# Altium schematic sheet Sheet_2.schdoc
size 319 x 192 mm
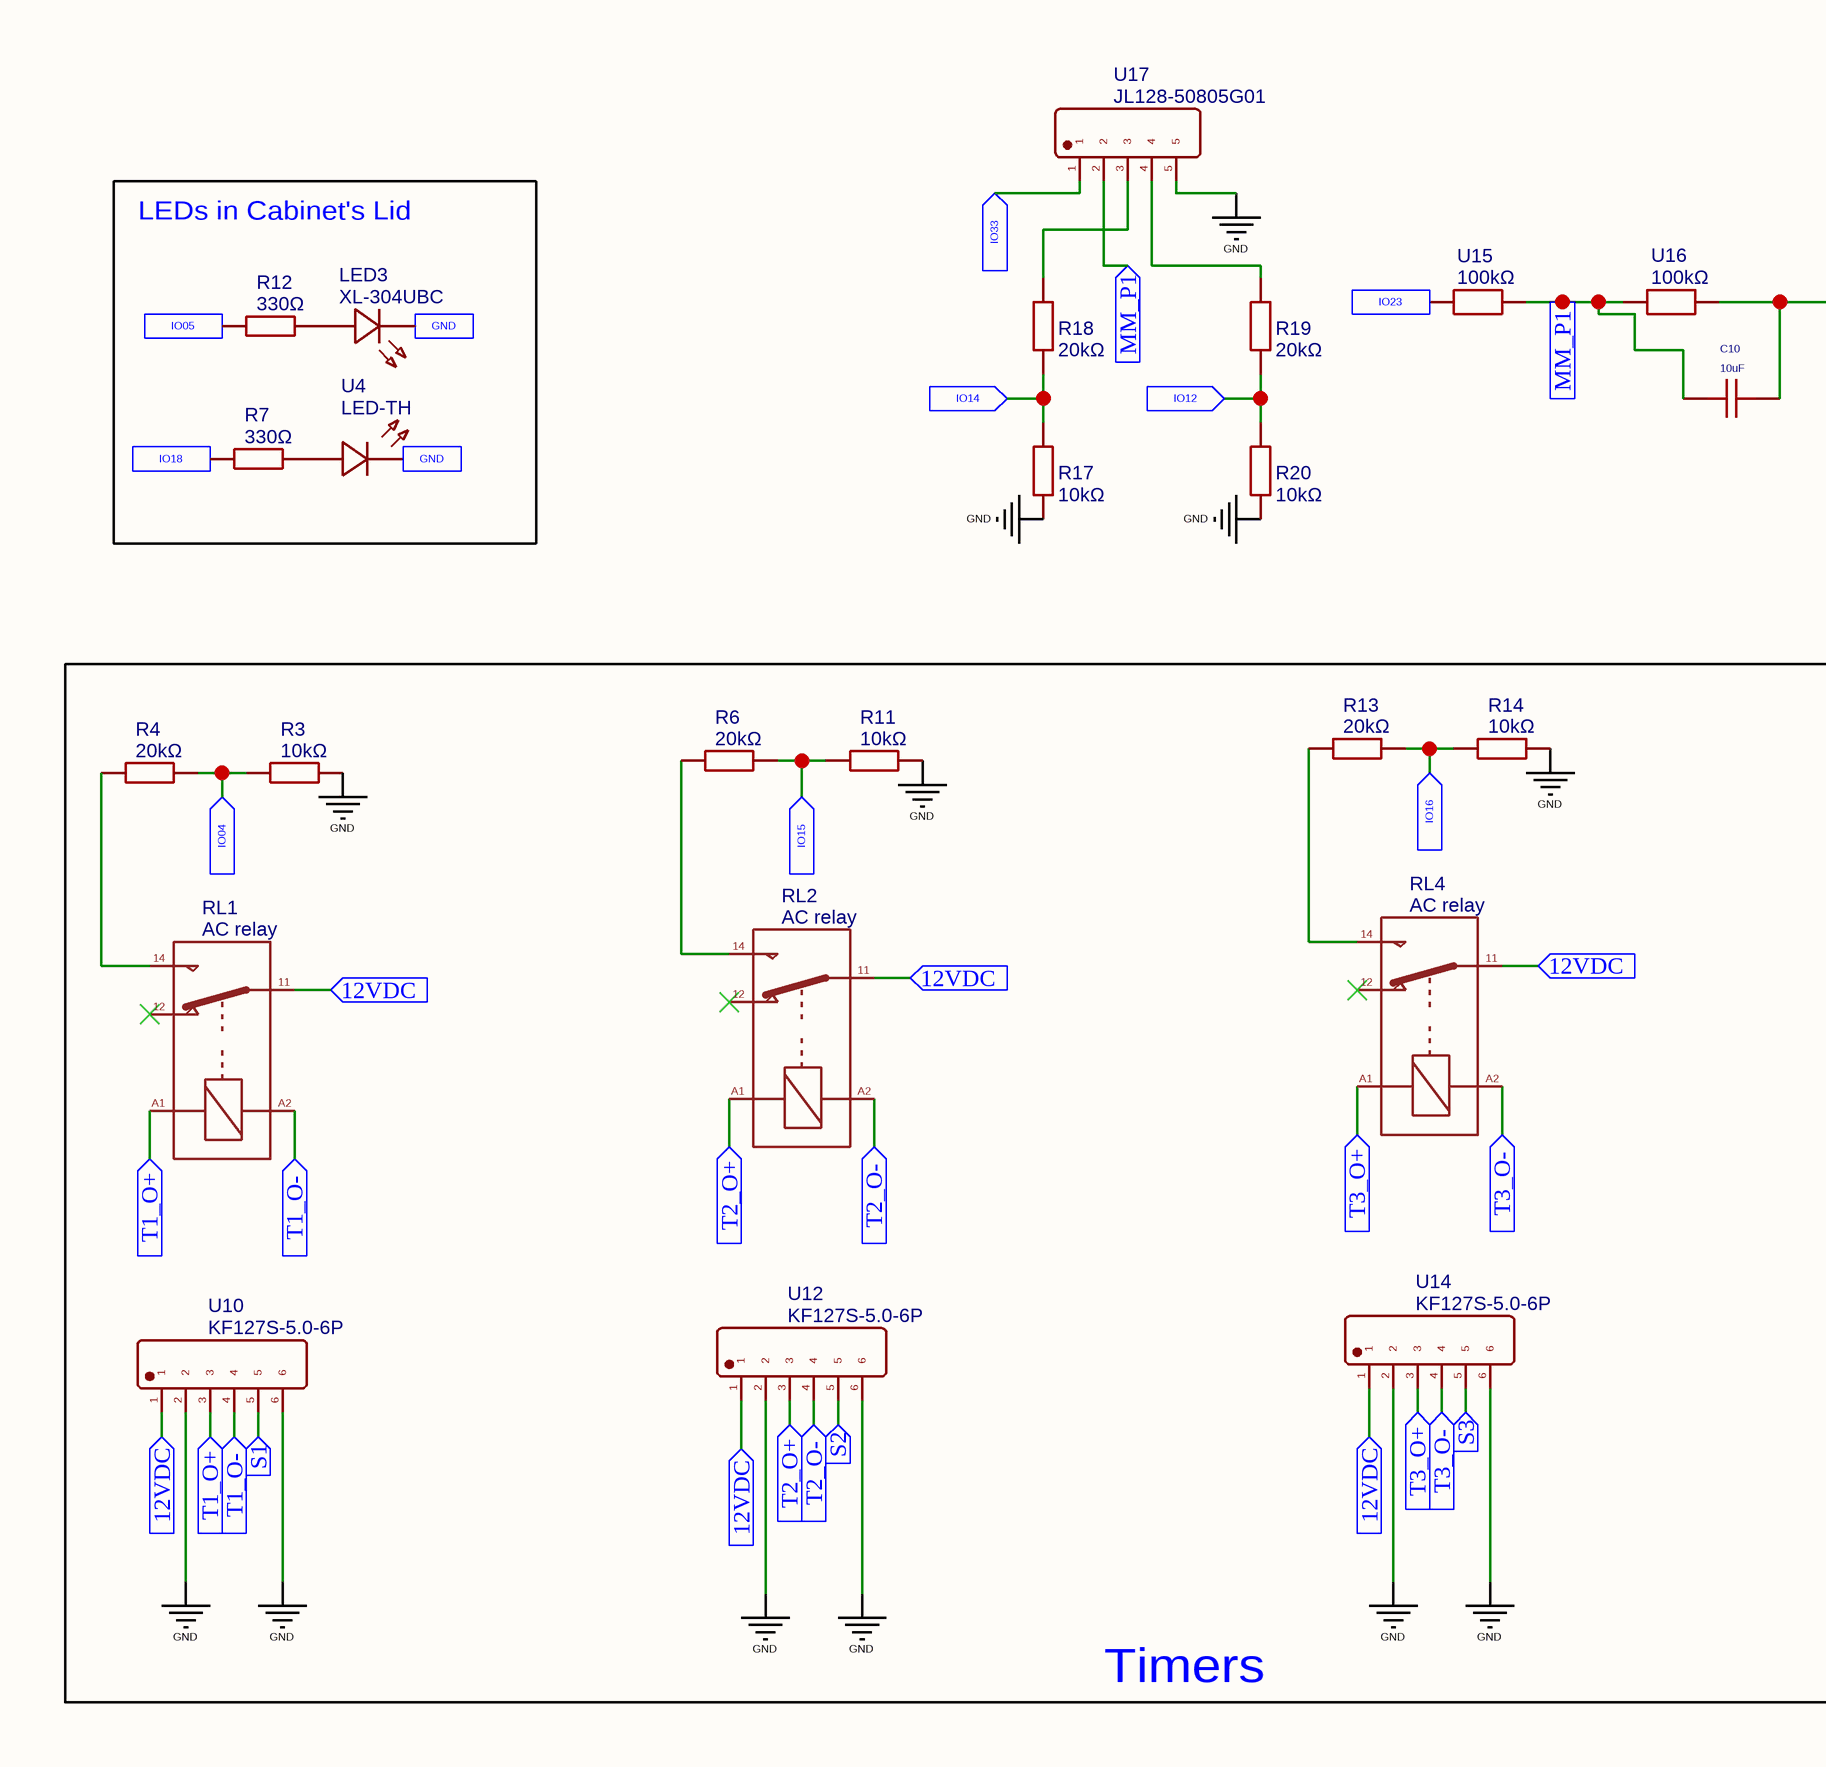
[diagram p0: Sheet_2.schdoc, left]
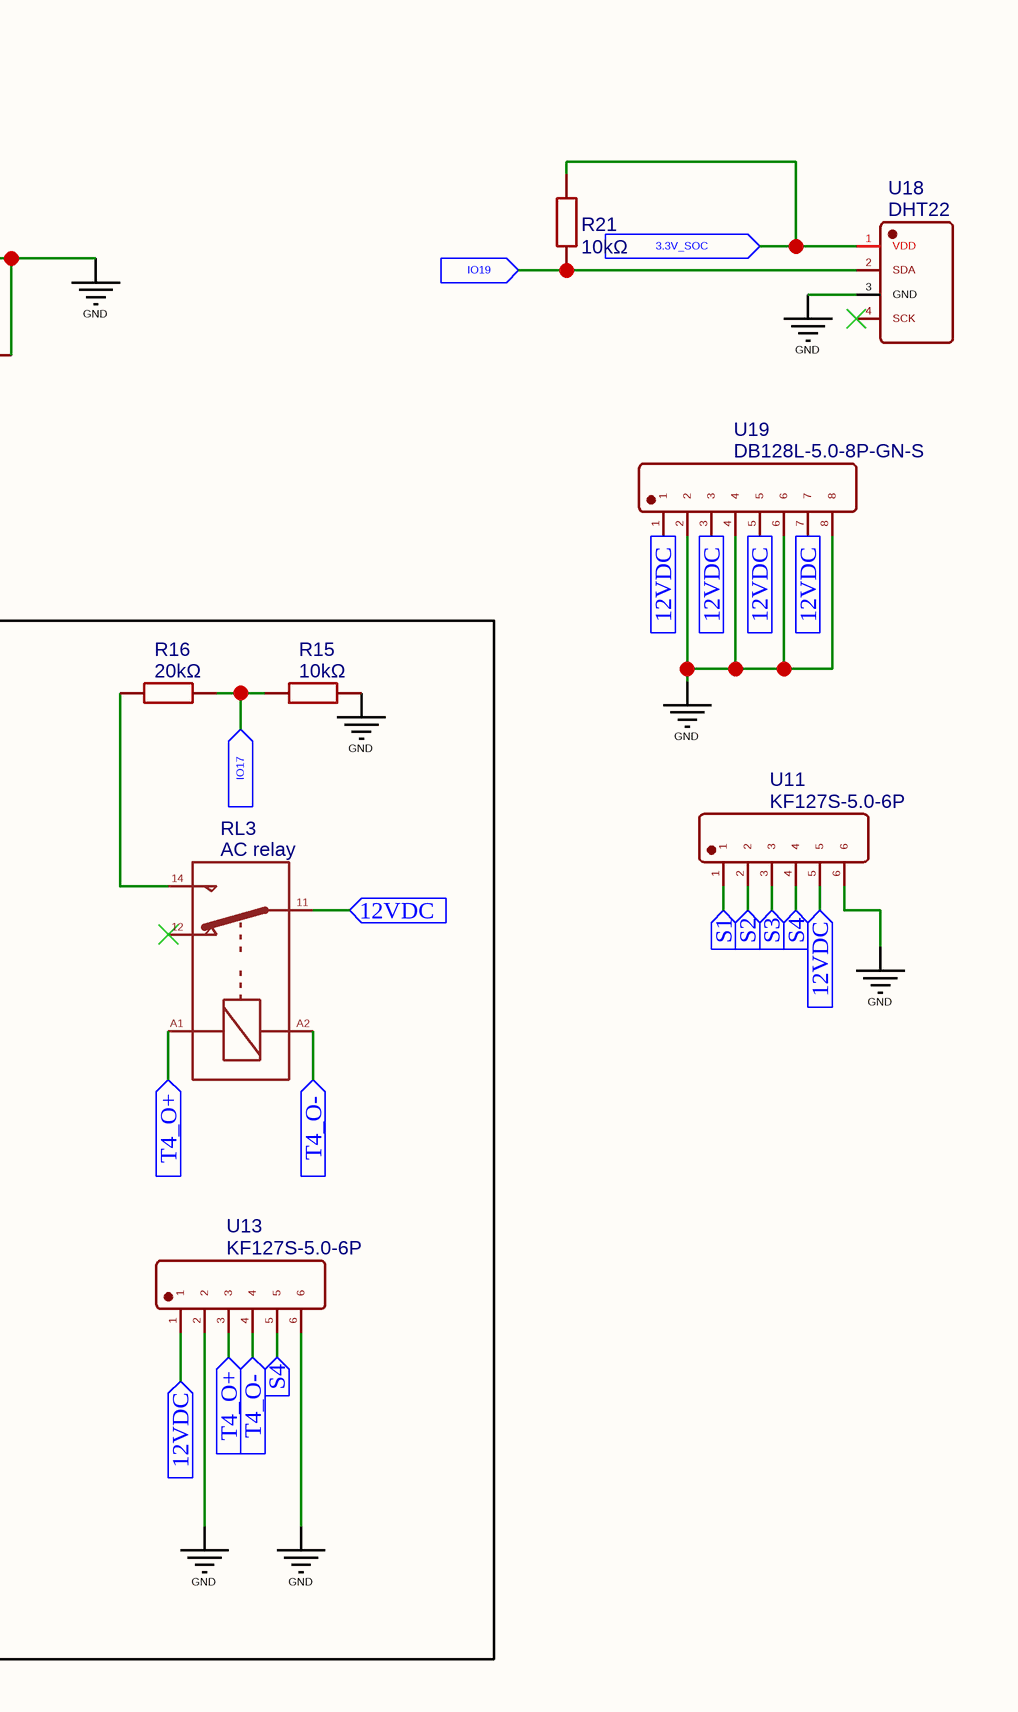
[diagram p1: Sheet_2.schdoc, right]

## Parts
C10  10uF  [C0603]
LED3  XL-304UBC  [LED-TH_BD3.8-P2.54-FD_BLUE]
R3  10kΩ  [RES-TH_BD2.3-L6.5-P10.50-D0.5]
R4  20kΩ  [RES-TH_BD2.3-L6.5-P10.50-D0.5]
R6  20kΩ  [RES-TH_BD2.3-L6.5-P10.50-D0.5]
R7  330Ω  [RES-TH_BD2.2-L6.5-P10.50-D0.6]
R11  10kΩ  [RES-TH_BD2.3-L6.5-P10.50-D0.5]
R12  330Ω  [RES-TH_BD2.2-L6.5-P10.50-D0.6]
R13  20kΩ  [RES-TH_BD2.3-L6.5-P10.50-D0.5]
R14  10kΩ  [RES-TH_BD2.3-L6.5-P10.50-D0.5]
R15  10kΩ  [RES-TH_BD2.3-L6.5-P10.50-D0.5]
R16  20kΩ  [RES-TH_BD2.3-L6.5-P10.50-D0.5]
R17  10kΩ  [RES-TH_BD2.3-L6.5-P10.50-D0.5]
R18  20kΩ  [RES-TH_BD2.3-L6.5-P10.50-D0.5]
R19  20kΩ  [RES-TH_BD2.3-L6.5-P10.50-D0.5]
R20  10kΩ  [RES-TH_BD2.3-L6.5-P10.50-D0.5]
R21  10kΩ  [RES-TH_BD2.3-L6.5-P10.50-D0.5]
RL1  AC relay  [FINDER RELAY 40.51]
RL2  AC relay  [FINDER RELAY 40.51]
RL3  AC relay  [FINDER RELAY 40.51]
RL4  AC relay  [FINDER RELAY 40.51]
U4  LED-TH  [LED-TH_BD3.8-P2.28_GREEN]
U10  KF127S-5.0-6P  [CONN-TH_6P-P5.00_KEFA_KF127S-5.0-6P]
U11  KF127S-5.0-6P  [CONN-TH_6P-P5.00_KEFA_KF127S-5.0-6P]
U12  KF127S-5.0-6P  [CONN-TH_6P-P5.00_KEFA_KF127S-5.0-6P]
U13  KF127S-5.0-6P  [CONN-TH_6P-P5.00_KEFA_KF127S-5.0-6P]
U14  KF127S-5.0-6P  [CONN-TH_6P-P5.00_KEFA_KF127S-5.0-6P]
U15  100kΩ  [RES-TH_BD2.5-L6.5-P10.50-D0.6]
U16  100kΩ  [RES-TH_BD2.5-L6.5-P10.50-D0.6]
U17  JL128-50805G01  [CONN-TH_JL128-50005G01]
U18  DHT22  [SENSOR-TH_HAIGU_DHT22]
U19  DB128L-5.0-8P-GN-S  [CONN-TH_8P-P5.00_DB128L-5.0-8P-GN-S]

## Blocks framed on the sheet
LEDs in Cabinet's Lid: LED3 R7 R12 U4
Timers: R3 R4 R6 R11 R13-R16 RL1-RL4 U10 U12-U14

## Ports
3.3V_SOC (in), 12VDC (in), GND (in), IO04 (in), IO05 (in), IO12 (in), IO14 (in), IO15 (in), IO16 (in), IO17 (in), IO18 (in), IO19 (in), IO23 (in), IO33 (in), MM_P1 (in), S1 (in), S2 (in), S3 (in), S4 (in), T1_O+ (in), T1_O- (in), T2_O+ (in), T2_O- (in), T3_O+ (in), T3_O- (in), T4_O+ (in), T4_O- (in)

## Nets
GND: C10.2 R3.2 R11.2 R14.2 R15.2 R17.2 R20.2 U10.2 U10.6 U11.6 U12.2 U12.6 U13.2 U13.6 U14.2 U14.6 U16.1 U17.5 U18.3(GND) U19.2 U19.4 U19.6 U19.8
3.3V_SOC: R21.2 U18.1(VDD) ; port 3.3V_SOC
12VDC: RL1.11 RL2.11 RL3.11 RL4.11 U10.1 U11.5 U12.1 U13.1 U14.1 U19.1 U19.3 U19.5 U19.7 ; port 12VDC
GND: LED3.2(K) U4.2(K) ; port GND  [a separate net that carries the same name]
IO04: R3.1 R4.2 ; port IO04
IO05: R12.1 ; port IO05
IO12: R19.2 R20.1 ; port IO12
IO14: R17.1 R18.2 ; port IO14
IO15: R6.2 R11.1 ; port IO15
IO16: R13.2 R14.1 ; port IO16
IO17: R15.1 R16.2 ; port IO17
IO18: R7.1 ; port IO18
IO19: R21.1 U18.2(SDA) ; port IO19
IO23: U15.2 ; port IO23
IO33: U17.1 ; port IO33
MM_P1: C10.1 U15.1 U16.2 U17.2 ; port MM_P1
S1: U10.5 U11.1 ; port S1
S2: U11.2 U12.5 ; port S2
S3: U11.3 U14.5 ; port S3
S4: U11.4 U13.5 ; port S4
T1_O+: RL1.A1 U10.3 ; port T1_O+
T1_O-: RL1.A2 U10.4 ; port T1_O-
T2_O+: RL2.A1 U12.3 ; port T2_O+
T2_O-: RL2.A2 U12.4 ; port T2_O-
T3_O+: RL4.A1 U14.3 ; port T3_O+
T3_O-: RL4.A2 U14.4 ; port T3_O-
T4_O+: RL3.A1 U13.3 ; port T4_O+
T4_O-: RL3.A2 U13.4 ; port T4_O-
NetLED3_1: LED3.1(A) R12.2
NetR4_1: R4.1 RL1.14
NetR6_1: R6.1 RL2.14
NetR7_2: R7.2 U4.1(A)
NetR13_1: R13.1 RL4.14
NetR16_1: R16.1 RL3.14
NetR18_1: R18.1 U17.3
NetR19_1: R19.1 U17.4

Not connected (* = marked no-connect by the designer): RL1 12*; RL2 12*; RL3 12*; RL4 12*; U18 4(SCK)*

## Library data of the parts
C10 = 10uF: BOM_Manufacturer: Walsin(华新科); BOM_Manufacturer Part: 0603X106K100CT; Contributor: LCSC; nameAlias: Capacitance
LED3 = XL-304UBC: BOM_Manufacturer: XINGLIGHT(成兴光); Contributor: lcsc
R3 R11 R14 R15 R17 R20 R21 = 10kΩ: BOM_Manufacturer: CCO(千志电子); BOM_Manufacturer Part: MF1/4W-10KΩ±1% T; Resistance (Ohms): 10K; nameAlias: Resistance; Contributor: LCSC
R4 R6 R13 R16 R18 R19 = 20kΩ: BOM_Manufacturer: CCO(千志电子); BOM_Manufacturer Part: CF1/4W-20KΩ±5% T; Resistance (Ohms): 20K; nameAlias: Resistance; Contributor: LCSC
R7 R12 = 330Ω: BOM_Manufacturer: KOA; BOM_Manufacturer Part: MF1/4CCT52A3300F; Resistance (Ohms): 330; nameAlias: Resistance; Contributor: LCSC
RL1-RL4 = AC relay: Contributor: yousif hassan; sourceId: HDnhbHngy
U4 = LED-TH: BOM_Manufacturer: null; BOM_Manufacturer Part: 绿发翠绿φ3直插长脚28mm; Contributor: LCSC
U10-U14 = KF127S-5.0-6P: BOM_Manufacturer: KEFA(科发); Contributor: LCSC
U15 U16 = 100kΩ: BOM_Manufacturer: 华星机电; BOM_Manufacturer Part: RI40-1/4W-100KΩ±1%T; Contributor: lcsc; nameAlias: Resistance
U17 = JL128-50805G01: BOM_Manufacturer: JILN(锦凌); Contributor: LCSC
U18 = DHT22: BOM_Manufacturer: HAIGU(广州海谷); Contributor: LCSC
U19 = DB128L-5.0-8P-GN-S: BOM_Manufacturer: DIBO(地博电气); Contributor: LCSC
